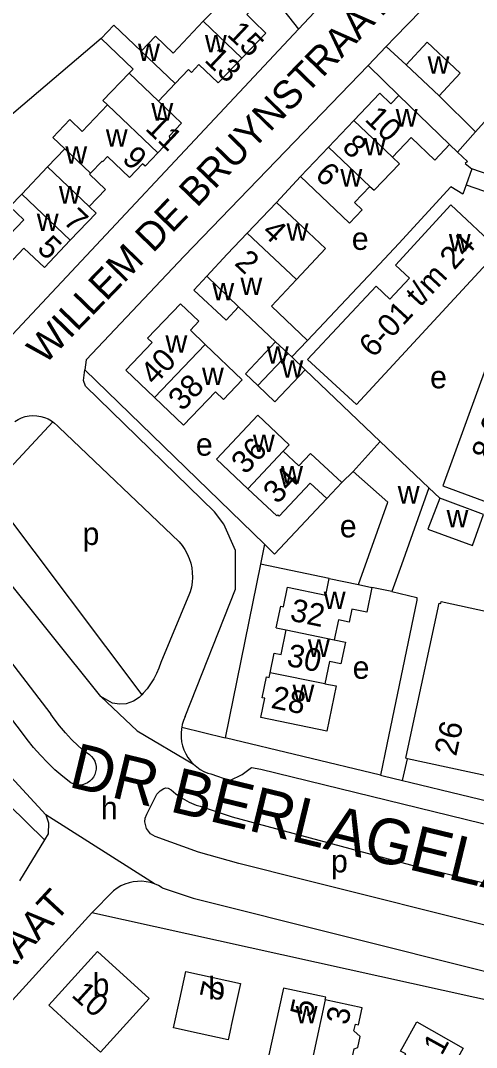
# Model space of a CAD drawing. Extents: x 159294 to 161936, y 384538 to 386517.
# Drawn here: x 160565.7 to 160646.3, y 385318.7 to 385500.1 of the extents above; entities that cross this region are included whole.
import ezdxf

# ---------------------------------------------------------------- set-up
doc = ezdxf.new("R2010")
doc.units = 0
for name, color, linetype in [('BLT_Basislijn', 7, 'Continuous'), ('BLT_Bebouwing', 7, 'Continuous'), ('BLT_Centroide', 7, 'Continuous'), ('BLT_Huisnummer', 7, 'Continuous'), ('BLT_Huisnummer_ tussenligend', 7, 'Continuous'), ('BLT_Huisnummer_reeks', 7, 'Continuous'), ('BLT_Onderverdeling_panden', 7, 'Continuous'), ('BLT_Straatnaam', 7, 'Continuous'), ('BLT_Straatnaam_hoofdweg', 7, 'Continuous'), ('BLT_Vlakafsluiter', 7, 'Continuous')]:
    doc.layers.add(name, color=color, linetype=linetype)

msp = doc.modelspace()

# ---------------------------------------------------------------- linework, layer by layer
at = {"layer": 'BLT_Basislijn'}
for p, q in [((160609.09, 385505.89), (160614.88, 385498.6)), ((160631.96, 385497.16), (160640.77, 385506.28)), ((160614.88, 385498.6), (160618.6, 385502.56)), ((160551.81, 385431.37), (160614.88, 385498.6)), ((160630.37, 385495.51), (160631.96, 385497.16)), ((160630.37, 385495.51), (160633.87, 385492.28)), ((160632.6, 385486.89), (160627.15, 385492.18)), ((160639.71, 385486.79), (160646.18, 385480.46)), ((160646.18, 385480.46), (160647.7, 385482.18)), ((160643, 385476.86), (160646.18, 385480.46)), ((160641.56, 385478.21), (160643, 385476.86)), ((160615.23, 385472.54), (160610.96, 385467.99)), ((160641.81, 385470.72), (160632.62, 385460.73)), ((160577.32, 385440.15), (160577.09, 385438.39)), ((160608.85, 385407.59), (160577.09, 385438.39)), ((160572.49, 385428.25), (160593.77, 385408.01)), ((160624.51, 385420.45), (160622.5, 385418.47)), ((160639.84, 385415.7), (160637.91, 385417.54)), ((160560.36, 385416.57), (160587.15, 385381)), ((160619.84, 385415.64), (160610.64, 385405.85)), ((160579.87, 385380.7), (160554.9, 385411.79)), ((160608.85, 385407.59), (160608.13, 385404.05)), ((160608.85, 385407.59), (160610.64, 385405.85)), ((160608.13, 385404.05), (160601.88, 385373.41)), ((160620.3, 385401.56), (160608.13, 385404.05)), ((160554.12, 385399.56), (160571.05, 385377.58)), ((160595.59, 385398.87), (160590.5, 385386.72)), ((160566.74, 385373.27), (160549.43, 385395.99)), ((160594.2, 385375.25), (160601.88, 385373.41)), ((160629.36, 385366.8), (160601.88, 385373.41)), ((160630.49, 385372.23), (160629.36, 385366.8)), ((160633.25, 385365.86), (160634.11, 385369.7)), ((160569.96, 385355.38), (160565.49, 385348.1)), ((160578.3, 385342.47), (160582.15, 385346.36))]:
    msp.add_line(p, q, dxfattribs=at)
for points in [[(160579.94, 385496.91), (160539.51, 385462.59), (160533, 385456.54)], [(160627.15, 385492.18), (160630.37, 385495.51)], [(160577.32, 385440.15), (160594.62, 385458.46), (160627.15, 385492.18)], [(160643, 385476.86), (160644.73, 385475.23), (160644.34, 385474.84), (160645.5, 385473.93)], [(160644.51, 385471.08), (160643.9, 385469.43), (160641.81, 385470.72)], [(160616.42, 385443.61), (160629.18, 385457.09), (160632.62, 385460.73)], [(160594.82, 385377.14), (160603.72, 385399.66), (160603.72, 385406.5), (160601.65, 385411.13), (160599.98, 385413.34), (160577.2, 385435.52), (160576.85, 385436.52), (160577.09, 385438.39)], [(160629.31, 385425.75), (160616.04, 385438.4)], [(160564.66, 385429.3), (160565.25, 385429.65), (160565.88, 385429.93), (160566.54, 385430.14), (160567.21, 385430.26), (160567.9, 385430.31), (160568.59, 385430.28), (160569.27, 385430.17), (160569.93, 385429.99), (160570.57, 385429.72), (160571.17, 385429.39), (160571.42, 385429.21)], [(160560.36, 385416.57), (160563.03, 385420.22), (160571.42, 385429.21)], [(160571.42, 385429.21), (160571.73, 385428.98), (160572.24, 385428.52), (160572.49, 385428.25)], [(160593.77, 385408.01), (160594.31, 385407.34), (160594.78, 385406.63), (160595.19, 385405.87), (160595.52, 385405.08), (160595.79, 385404.26), (160595.97, 385403.42), (160596.07, 385402.57), (160596.1, 385401.71), (160596.04, 385400.86), (160595.91, 385400.01), (160595.69, 385399.18), (160595.59, 385398.87)], [(160631.37, 385399.24), (160635.77, 385398.2), (160635.77, 385397.69), (160630.49, 385372.23)], [(160543.23, 385392.86), (160559.04, 385371.44), (160559.83, 385370.9), (160570.17, 385359.77)], [(160590.5, 385386.72), (160590.16, 385385.72), (160589.75, 385384.75), (160589.26, 385383.81), (160588.7, 385382.91), (160588.08, 385382.06), (160587.4, 385381.25), (160587.15, 385381)], [(160587.15, 385381), (160586.65, 385380.5), (160585.68, 385379.88), (160584.4, 385379.39), (160583.2, 385379.34), (160581.96, 385379.5), (160579.87, 385380.7)], [(160549.7, 385378.57), (160552.12, 385375.42), (160557.29, 385367.72), (160569.96, 385355.38)], [(160577.06, 385370.92), (160575.86, 385371.97), (160574.71, 385373.09), (160573.62, 385374.26), (160572.59, 385375.48), (160571.62, 385376.76), (160571.05, 385377.58)], [(160594.82, 385377.14), (160594.52, 385376.44), (160594.29, 385375.72), (160594.2, 385375.25)], [(160594.2, 385375.25), (160594.15, 385374.97), (160594.08, 385374.22), (160594.09, 385373.46), (160594.18, 385372.7), (160594.35, 385371.96), (160594.59, 385371.24), (160594.91, 385370.56), (160595.3, 385369.91), (160595.76, 385369.3), (160596.28, 385368.75)], [(160574.58, 385365.43), (160573.16, 385366.57), (160571.79, 385367.76), (160570.47, 385369.02), (160569.21, 385370.33), (160568.01, 385371.69), (160566.87, 385373.11), (160566.74, 385373.27)], [(160577.06, 385370.92), (160577.51, 385370.72), (160577.91, 385370.44), (160578.27, 385370.11), (160578.57, 385369.72), (160578.81, 385369.29), (160578.97, 385368.83), (160579.05, 385368.34), (160579.06, 385367.85), (160578.98, 385367.36), (160578.83, 385366.9), (160578.6, 385366.46), (160578.31, 385366.07), (160577.95, 385365.73), (160577.55, 385365.45), (160577.1, 385365.24), (160576.63, 385365.11), (160576.14, 385365.05), (160575.65, 385365.08), (160575.17, 385365.18), (160574.71, 385365.36), (160574.58, 385365.43)], [(160596.28, 385368.75), (160596.85, 385368.25), (160597.48, 385367.82), (160598.14, 385367.45), (160598.84, 385367.16), (160599.33, 385367)], [(160604.87, 385366.92), (160606.52, 385368.14), (160608.19, 385367.83), (160652.77, 385356.97), (160654.51, 385353.93), (160660.49, 385352.61)], [(160599.33, 385367), (160602.71, 385365.87), (160604.87, 385366.92)], [(160629.36, 385366.8), (160629.84, 385366.69), (160633.25, 385365.86)], [(160589.52, 385355.96), (160588.7, 385356.44), (160587.98, 385357.38), (160587.7, 385358.56), (160587.74, 385359.19), (160588.01, 385359.89), (160589.83, 385363.45), (160590.4, 385364.05), (160591.03, 385364.46), (160591.4, 385364.53), (160591.79, 385364.51), (160592.35, 385364.21), (160593.16, 385363.51), (160594.31, 385362.71), (160595.53, 385362.04), (160596.76, 385361.52), (160597.46, 385361.3)], [(160633.25, 385365.86), (160634.7, 385365.51), (160669.84, 385357.03)], [(160597.46, 385361.3), (160603.12, 385359.41), (160634.68, 385350.95)], [(160570.17, 385359.77), (160570.63, 385358.36), (160570.61, 385356.43), (160569.96, 385355.38)], [(160650.43, 385339.64), (160650.15, 385339.7), (160615.82, 385348.32), (160604.29, 385351.19), (160597.16, 385353.16), (160589.52, 385355.96)], [(160634.68, 385350.95), (160653.65, 385346.3), (160654.19, 385346.17)], [(160589.4, 385347.57), (160588.67, 385347.8), (160587.92, 385347.96), (160587.15, 385348.04), (160586.39, 385348.03), (160585.63, 385347.95), (160584.88, 385347.78), (160584.15, 385347.54), (160583.46, 385347.23), (160582.8, 385346.84), (160582.15, 385346.36)], [(160590.76, 385346.89), (160590.1, 385347.27), (160589.4, 385347.57)], [(160590.76, 385346.89), (160596.24, 385345.06), (160648.46, 385332)], [(160578.3, 385342.47), (160532.7, 385292.36), (160531.3, 385289.81), (160548.08, 385259.76), (160549.53, 385257.91)], [(160651.66, 385326.26), (160578.3, 385342.47)]]:
    msp.add_lwpolyline(points, dxfattribs=at)
at = {"layer": 'BLT_Bebouwing'}
for p, q in [((160633.87, 385492.28), (160639.71, 385486.79)), ((160593.03, 385488.98), (160590.11, 385485.85)), ((160629.24, 385487.27), (160624.66, 385482.46)), ((160624.66, 385482.46), (160620.19, 385477.76)), ((160570.48, 385474.28), (160573.52, 385477.47)), ((160620.19, 385477.76), (160615.23, 385472.54)), ((160570.48, 385474.28), (160565.9, 385469.45)), ((160645.5, 385473.93), (160644.51, 385471.08)), ((160644.51, 385471.08), (160655.76, 385467.19)), ((160605.78, 385462.55), (160610.96, 385467.99)), ((160610.81, 385443.32), (160604.25, 385449.55)), ((160637.91, 385417.54), (160629.31, 385425.75)), ((160647.55, 385412.85), (160639.84, 385415.7)), ((160631.37, 385399.24), (160627.82, 385399.97)), ((160610.93, 385392.8), (160612.67, 385392.44))]:
    msp.add_line(p, q, dxfattribs=at)
for points in [[(160598.01, 385500.01), (160600.45, 385502.49), (160598.89, 385503.99), (160600.44, 385505.6), (160599.16, 385506.83), (160600.91, 385508.64)], [(160609.09, 385505.89), (160606.44, 385503.17), (160607.07, 385502.56), (160605.7, 385501.15), (160606.89, 385500)], [(160579.94, 385496.91), (160582.22, 385499.3), (160587.02, 385494.72)], [(160587.02, 385494.72), (160589.54, 385497.35), (160592.67, 385494.37), (160598.01, 385500.01)], [(160604.84, 385493.49), (160609.05, 385497.9), (160606.89, 385500)], [(160584.91, 385490.81), (160585.59, 385491.52), (160579.94, 385496.91)], [(160639.71, 385486.79), (160643.47, 385490.79), (160637.63, 385496.28), (160633.87, 385492.28)], [(160593.03, 385488.98), (160595.39, 385491.45), (160595.92, 385490.94), (160597.24, 385492.33), (160600.64, 385489.09), (160604.84, 385493.49)], [(160581.06, 385485.23), (160580.28, 385485.97), (160584.91, 385490.81)], [(160632.6, 385486.89), (160631.19, 385485.41), (160629.24, 385487.27)], [(160641.56, 385478.21), (160632.6, 385486.89)], [(160573.52, 385477.47), (160571.41, 385479.47), (160574.41, 385482.61), (160576.59, 385480.52), (160581.06, 385485.23)], [(160590.11, 385485.85), (160594.18, 385481.95), (160592, 385479.68), (160592.18, 385479.04), (160589.99, 385476.74)], [(160631.46, 385475.99), (160634.76, 385479.47), (160638.96, 385475.47), (160641.56, 385478.21)], [(160589.99, 385476.74), (160587.73, 385474.38), (160587.28, 385474.8), (160584.96, 385472.38), (160581.09, 385476.08), (160580.22, 385475.17), (160580.12, 385475.27), (160578.08, 385473.14)], [(160627.49, 385470.81), (160628.22, 385470.12), (160632.69, 385474.82), (160631.46, 385475.99)], [(160655.76, 385467.19), (160656.75, 385470.04), (160645.5, 385473.93)], [(160578.08, 385473.14), (160577.9, 385472.95), (160580.73, 385470.26), (160577.85, 385467.27)], [(160615.23, 385472.54), (160618.85, 385469.1), (160623.89, 385464.3), (160626.13, 385466.65), (160624.77, 385467.95), (160627.49, 385470.81)], [(160565.9, 385469.45), (160563.81, 385467.26), (160566.28, 385464.92), (160563.76, 385462.27), (160560.42, 385465.45), (160558.02, 385462.93), (160557.56, 385462.44)], [(160610.96, 385467.99), (160614.61, 385464.57), (160619.65, 385459.85), (160614.52, 385454.37)], [(160574.5, 385461.28), (160579.09, 385466.1), (160577.85, 385467.27)], [(160598.64, 385454.96), (160602.25, 385458.83), (160605.78, 385462.55)], [(160660.02, 385464.02), (160656.42, 385454.22), (160653.99, 385455.11), (160653.06, 385452.59), (160655.43, 385451.73), (160654.67, 385449.65), (160652.31, 385450.53), (160640.36, 385417.92), (160651.38, 385413.83), (160655.52, 385425.12), (160652.37, 385426.27), (160654.12, 385431.03), (160657.27, 385429.88), (160663.37, 385446.52), (160660.22, 385447.68), (160660.94, 385449.65), (160661.69, 385449.37), (160661.8, 385449.69)], [(160563.43, 385456.87), (160566.3, 385459.89), (160569.92, 385456.45), (160574.5, 385461.28)], [(160596.32, 385452.48), (160598.64, 385454.96)], [(160614.52, 385454.37), (160610.08, 385449.63), (160616.42, 385443.61)], [(160604.25, 385449.55), (160602.05, 385447.18), (160596.32, 385452.48)], [(160589.39, 385433.49), (160584.3, 385438.37), (160588.95, 385443.23), (160588.15, 385443.99), (160593.99, 385450.08)], [(160593.99, 385450.08), (160597.25, 385446.97), (160595.73, 385445.38), (160598.36, 385442.86)], [(160598.36, 385442.86), (160604.88, 385436.62), (160601.58, 385433.18), (160600.16, 385434.54), (160594.49, 385428.61), (160589.39, 385433.49)], [(160607.66, 385435.61), (160605.46, 385437.69), (160610.81, 385443.32)], [(160613.65, 385440.68), (160616.42, 385443.61)], [(160616.04, 385438.4), (160613.65, 385440.68)], [(160616.04, 385438.4), (160610.67, 385432.75), (160607.66, 385435.61)], [(160612.16, 385424.04), (160613.21, 385425.17), (160607.68, 385430.37), (160604.02, 385426.48), (160600.38, 385422.6), (160605.92, 385417.4)], [(160624.51, 385420.45), (160629.31, 385425.75)], [(160612.16, 385424.04), (160614.93, 385421.43), (160617, 385423.64), (160622.5, 385418.47)], [(160625.46, 385400.5), (160630.66, 385415), (160624.51, 385420.45)], [(160619.84, 385415.64), (160616.9, 385418.4), (160611.42, 385412.57), (160611.18, 385412.8), (160611, 385412.62), (160605.92, 385417.4)], [(160622.5, 385418.47), (160619.84, 385415.64)], [(160637.91, 385417.54), (160633.06, 385403.95), (160631.37, 385399.24)], [(160639.84, 385415.7), (160637.74, 385410.24), (160645.61, 385407.34), (160647.55, 385412.85)], [(160610.93, 385392.8), (160611.72, 385396.64), (160612.23, 385396.53), (160612.93, 385399.98), (160619.69, 385398.59), (160620.3, 385401.56)], [(160620.3, 385401.56), (160625.46, 385400.5)], [(160627.82, 385399.97), (160626.92, 385395.59), (160624.3, 385396.12), (160623.84, 385393.83), (160621.91, 385394.22), (160621.19, 385390.7)], [(160634.11, 385369.7), (160633.81, 385369.77), (160634.95, 385375.02), (160639.76, 385397.18), (160640.01, 385397.13), (160640.08, 385397.48), (160667.91, 385391.43), (160672.79, 385390.37), (160672.72, 385390.03), (160673.02, 385389.96)], [(160609.87, 385384.89), (160610.58, 385388.37), (160611.78, 385388.08), (160612.67, 385392.44)], [(160621.19, 385390.7), (160623.14, 385390.3), (160622.35, 385386.48), (160620.33, 385386.89), (160619.52, 385382.91)], [(160619.85, 385374.58), (160608.18, 385376.97), (160608.88, 385380.38), (160608.42, 385380.48), (160609.17, 385384.14), (160609.69, 385384.03), (160609.87, 385384.89)], [(160619.52, 385382.91), (160621.49, 385382.6), (160619.85, 385374.58)], [(160656.27, 385364.89), (160634.11, 385369.7)], [(160588.42, 385327.33), (160579.84, 385317.85), (160574.4, 385322.77), (160570.69, 385326.13), (160579.3, 385335.65), (160588.42, 385327.33)], [(160604.57, 385329.96), (160602.95, 385322.57), (160602.87, 385322.21), (160602.39, 385320.02), (160597.29, 385321.14), (160592.73, 385322.14), (160593.84, 385327.2), (160594.91, 385332.08), (160604.57, 385329.96)], [(160619.57, 385327.08), (160619.67, 385327.55), (160612.21, 385329.17), (160609.48, 385316.88)], [(160627.27, 385311.03), (160627.98, 385314.27), (160623.98, 385315.14), (160624.7, 385318.45), (160625.35, 385318.66), (160625.77, 385320.6), (160624.66, 385321.61), (160624.92, 385322.81), (160625.45, 385322.69), (160626.1, 385325.66), (160619.57, 385327.08)], [(160631.33, 385310.58), (160632.11, 385314.4), (160633.84, 385317.55), (160632.92, 385318.05), (160633.36, 385318.84), (160635.77, 385323.22), (160643.98, 385318.55), (160641.4, 385313.88), (160640.77, 385314.23), (160638.77, 385310.6), (160636.94, 385307.56)]]:
    msp.add_lwpolyline(points, dxfattribs=at)
msp.add_lwpolyline([(160641.81, 385467.57), (160650.37, 385459.57), (160625.09, 385432.3), (160616.44, 385440.24), (160628.57, 385453.17), (160631.03, 385450.89), (160634.47, 385454.62), (160632.01, 385456.9)], close=True, dxfattribs=at)
at = {"layer": 'BLT_Onderverdeling_panden'}
for p, q in [((160604.84, 385493.49), (160598.01, 385500.01)), ((160593.03, 385488.98), (160587.02, 385494.72)), ((160584.91, 385490.81), (160590.11, 385485.85)), ((160589.99, 385476.74), (160581.06, 385485.23)), ((160631.46, 385475.99), (160624.66, 385482.46)), ((160578.08, 385473.14), (160573.52, 385477.47)), ((160627.49, 385470.81), (160620.19, 385477.76)), ((160570.48, 385474.28), (160577.85, 385467.27)), ((160574.5, 385461.28), (160565.9, 385469.45)), ((160614.52, 385454.37), (160605.78, 385462.55)), ((160598.64, 385454.96), (160604.25, 385449.55)), ((160589.39, 385433.49), (160598.36, 385442.86)), ((160610.81, 385443.32), (160613.03, 385441.26)), ((160607.66, 385435.61), (160613.03, 385441.26)), ((160613.03, 385441.26), (160613.65, 385440.68)), ((160605.92, 385417.4), (160612.16, 385424.04)), ((160625.46, 385400.5), (160627.82, 385399.97)), ((160612.67, 385392.44), (160621.19, 385390.7)), ((160619.52, 385382.91), (160609.87, 385384.89)), ((160619.57, 385327.08), (160617.25, 385316.42))]:
    msp.add_line(p, q, dxfattribs=at)
at = {"layer": 'BLT_Vlakafsluiter'}
msp.add_line((160589.4, 385347.57), (160570.17, 385359.77), dxfattribs=at)
msp.add_lwpolyline([(160579.87, 385380.7), (160586.3, 385374.61), (160596.28, 385368.75)], dxfattribs=at)

# ---------------------------------------------------------------- texts
at = {"layer": 'BLT_Centroide'}
for s, p in [('w', (160598.3, 385494.5)), ('w', (160586.48, 385492.94)), ('w', (160637.69, 385490.71)), ('w', (160588.83, 385482.44)), ('w', (160632.05, 385481.38)), ('w', (160580.78, 385477.84)), ('w', (160626.44, 385476.28)), ('w', (160573.62, 385474.84)), ('w', (160622.27, 385470.78)), ('w', (160572.49, 385467.78)), ('w', (160568.57, 385462.94)), ('w', (160612.74, 385461.19)), ('e', (160624.28, 385459.59)), ('w', (160641.44, 385459.35)), ('w', (160599.62, 385450.68)), ('w', (160604.59, 385451.62)), ('w', (160591.33, 385441.41)), ('w', (160609.25, 385439.48)), ('w', (160597.79, 385435.72)), ('w', (160611.84, 385437.02)), ('e', (160638.13, 385435.13)), ('e', (160596.7, 385423.23)), ('w', (160606.8, 385423.89)), ('w', (160611.79, 385418.31)), ('w', (160632.41, 385414.78)), ('w', (160641.04, 385410.57)), ('e', (160622.16, 385408.8)), ('p', (160576.66, 385407.46)), ('w', (160619.32, 385396.12)), ('w', (160616.52, 385387.69)), ('e', (160624.43, 385383.82)), ('w', (160613.8, 385379.72)), ('h', (160579.89, 385358.99)), ('p', (160620.6, 385349.62)), ('b', (160578.44, 385327.78)), ('b', (160598.89, 385327.16)), ('w', (160614.36, 385322.95))]:
    msp.add_text(s, height=4, dxfattribs=at).set_placement(p)
at = {"layer": 'BLT_Huisnummer'}
for s, rotation, p in [('15', 316.4808, (160602.02, 385497.51)), ('13', 316.4808, (160598.05, 385492.98)), ('10', 316.434, (160626.39, 385482.51)), ('11', 316.4808, (160587.59, 385480.89)), ('9', 316.4808, (160583.48, 385475.45)), ('6', 316.4394, (160617.59, 385472.6)), ('7', 316.4808, (160573.07, 385464.46)), ('4', 316.8758, (160608.2, 385462.53)), ('2', 316.8674, (160603.37, 385457.08)), ('40', 46.7735, (160589.41, 385435.5)), ('38', 46.7735, (160594.34, 385430.95)), ('36', 46.7735, (160605.48, 385419.76)), ('34', 46.7735, (160611.12, 385414.53)), ('32', 348.4315, (160613.19, 385394.13)), ('28', 348.425, (160609.83, 385378.71)), ('10', 317.8752, (160574.53, 385327.77)), ('7', 77.5855, (160601.26, 385326.91)), ('5', 77.7151, (160617.21, 385323.86)), ('3', 77.6997, (160623.58, 385322.51)), ('1', 61.1562, (160640.19, 385317.12))]:
    msp.add_text(s, height=4, rotation=rotation, dxfattribs=at).set_placement(p)
at = {"layer": 'BLT_Huisnummer_ tussenligend'}
for s, rotation, p in [('8', 316.4394, (160622.37, 385477.51)), ('5', 316.4808, (160568.43, 385459.63)), ('30', 348.425, (160612.61, 385386.15))]:
    msp.add_text(s, height=4, rotation=rotation, dxfattribs=at).set_placement(p)
at = {"layer": 'BLT_Huisnummer_reeks'}
for s, rotation, p in [('6-01 t/m 24', 47.3812, (160628.11, 385440.37)), ('8-01 t/m 27', 71.3812, (160649.13, 385422.21)), ('26', 77.7389, (160642.73, 385370.01))]:
    msp.add_text(s, height=4, rotation=rotation, dxfattribs=at).set_placement(p)
at = {"layer": 'BLT_Straatnaam'}
for s, height, rotation, p in [('VAN NORENBURCHSTRAAT', 5, 36.8707, (160496.9, 385472.93)), ('WILLEM DE BRUYNSTRAAT', 4.9999, 45.8998, (160569.98, 385439.18)), ('PASQUALINISTRAAT', 5, 47.2565, (160529.49, 385294.84))]:
    msp.add_text(s, height=height, rotation=rotation, dxfattribs=at).set_placement(p)
at = {"layer": 'BLT_Straatnaam_hoofdweg'}
msp.add_text('DR BERLAGELAAN', height=8, rotation=346.3808, dxfattribs=at).set_placement((160573.97, 385364.78))

doc.saveas('drawing.dxf')
